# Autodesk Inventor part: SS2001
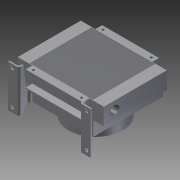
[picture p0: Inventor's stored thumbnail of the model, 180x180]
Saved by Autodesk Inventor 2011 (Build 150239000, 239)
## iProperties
Created: 2011-08
Part Number: SS2001
Document SubType Name: Modeling
Designer: khramov
Density: 1 g/cm^3
Author: khramov
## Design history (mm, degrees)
sketch "Эскиз1"
  geometry: L1 (0, 0)-(318, 0); L2 (318, 0)-(318, -283); L3 (318, -283)-(0, -283); L4 (0, -283)-(0, 0)
  constraints: 8 end point, 2 parallel, 1 horizontal, 1 perpendicular
  dimensions: "d0" = 318 distance of L1.start L1.end; "d1" = 283 distance of L3.end L1.start
extrude "Выдавливание1" new body sketch "Эскиз1" distance "d2" = 63; taper "d3" = 0 deg
sketch "Эскиз2"
  geometry: L1 (-63, 283)-(-63, 0) reference; L2 (0, 283)-(0, 0) reference; L3 (0, 283)-(-63, 283) reference; L4 (-58, 283)-(-5, 283); L5 (-5, 283)-(-5, 258); L6 (-5, 258)-(-58, 258); L7 (-58, 258)-(-58, 283); L8 (-63, 0)-(-63, 283) reference; L9 (-63, 141.5)-(63.697, 141.5); L10 (0, 0)-(-63, 0); L11 (-58, 0)-(-5, 0); L12 (-5, 0)-(-5, 25); L13 (-5, 25)-(-58, 25); L14 (-58, 25)-(-58, 0)
  constraints: 20 end point, 4 symmetric about line, 2 parallel, 2 perpendicular, 2 point on line, 1 horizontal, 1 midpoint
  dimensions: "d4" = 5 distance between parallel lines of L7 L1; "d5" = 5 distance between parallel lines of L2 L5; "d6" = 25 distance between parallel lines of L3 L6
extrude "Выдавливание2" cut sketch "Эскиз2" stored distance "d7" = 63; taper "d8" = 0 deg
sketch "Эскиз3"
  geometry: L1 (0, 0)-(54, 0); L2 (54, 0)-(54, -25); L3 (54, -25)-(0, -25); L4 (0, -25)-(0, 0); L5 (318, 0)-(264, 0); L6 (264, 0)-(264, -25); L7 (264, -25)-(318, -25); L8 (318, -25)-(318, 0); L9 (0, -141.5)-(444.092, -141.5); L10 (0, -283)-(54, -283); L11 (54, -283)-(54, -258); L12 (54, -258)-(0, -258); L13 (0, -258)-(0, -283); L14 (318, -283)-(264, -283); L15 (264, -283)-(264, -258); L16 (264, -258)-(318, -258); L17 (318, -258)-(318, -283)
  constraints: 34 end point, 8 symmetric about line, 4 parallel, 3 perpendicular, 2 horizontal
  dimensions: "d9" = 25 distance of L1.end L2.end; "d10" = 25 distance of L5.end L6.end; "d11" = 210 distance between parallel lines of L6 L2; "d13" = 54 distance of L2.end L3.end
extrude "Выдавливание3" cut sketch "Эскиз3" stored distance "d14" = 0; taper "d15" = 0 deg
sketch "Эскиз4"
  geometry: L1 (54, 0)-(54, -25) reference; L2 (54, 0)-(264, 0) reference; L3 (70, -12.5)-(248, -12.5); L4 (248, -12.5)-(248, -270.5); L5 (248, -270.5)-(70, -270.5); L6 (70, -270.5)-(70, -12.5); C1 r 4.5 at (70, -12.5); C2 r 4.5 at (248, -12.5); C3 r 4.5 at (248, -270.5); C4 r 4.5 at (70, -270.5); 1 further point
  constraints: 8 end point, 4 centre point, 4 coincident, 2 parallel, 1 horizontal, 1 perpendicular
  dimensions: "d16" = 9 diameter of C1; "d17" = 9 diameter of C2; "d18" = 9 diameter of C3; "d19" = 9 diameter of C4; "d20" = 258 distance of L5.end L3.start; "d21" = 178 distance of L3.start L3.end; "d22" = 16 distance between parallel lines of L6 L1; "d23" = 12.5 distance between parallel lines of L3 L2
extrude "Выдавливание4" cut sketch "Эскиз4" distance "d24" = 10; taper "d25" = 0 deg
sketch "Эскиз5"
  geometry: L1 (54, 0)-(54, -25) reference; L2 (54, -25)-(0, -25) reference; L3 (0, -258)-(54, -258) reference; L4 (264, -25)-(264, 0) reference; L5 (42, -27)-(276, -27); L6 (276, -27)-(276, -256); L7 (276, -256)-(42, -256); L8 (42, -256)-(42, -27); 1 further point
  constraints: 8 end point, 2 parallel, 1 horizontal, 1 perpendicular
  dimensions: "d26" = 2 distance between parallel lines of L5 L2; "d27" = 2 distance between parallel lines of L3 L7; "d28" = 12 distance between parallel lines of L1 L8; "d29" = 12 distance between parallel lines of L6 L4
extrude "Выдавливание5" cut sketch "Эскиз5" distance "d30" = 2; taper "d31" = 0 deg
sketch "Эскиз6"
  geometry: L1 (-264, 0)-(-264, -25) reference; L2 (-279, 0)-(-39, 0); L3 (-39, 0)-(-39, -258); L4 (-39, -258)-(-279, -258); L5 (-279, -258)-(-279, 0); 1 further point
  constraints: 8 end point, 2 parallel, 1 horizontal, 1 perpendicular
  dimensions: "d32" = 210 distance of point (-54, 0) L1.start (derived); "d33" = 240 distance between parallel lines of L3 L5; "d34" = 15 distance between parallel lines of L1 L5; "d35" = 258 distance of L4.end L2.start
extrude "Выдавливание6" join sketch "Эскиз6" distance "d36" = 53; taper "d37" = 0 deg
sketch "Эскиз7"
  geometry: L1 (-279, 0)-(-39, -258); L2 (-39, 0)-(-279, -258); C1 r 100 at (-159, -129); 1 further point
  constraints: 4 end point, 1 centre point, 1 midpoint
  dimensions: "d38" = 200 diameter of C1
extrude "Выдавливание7" join sketch "Эскиз7" distance "d39" = 54; taper "d40" = 0 deg
sketch "Эскиз8"
  geometry: L1 (-276.5, -265)-(-276.5, -288); L2 (-283.5, -295)-(-311.5, -295); L3 (-311.5, -295)-(-311.5, -300); L4 (-311.5, -300)-(-278.5, -300); L5 (-271.5, -293)-(-271.5, -270); L6 (-264.5, -263)-(-264, -263); L7 (-264, -258)-(-264, -263); L8 (-269.5, -258)-(-264, -258); L9 (-159, -129)-(-159, -359.645); L10 (-296.5, -281.5)-(-296.5, -330.929); L11 (-41.5, -265)-(-41.5, -288); L12 (-46.5, -293)-(-46.5, -270); L13 (-6.5, -300)-(-39.5, -300); L14 (-34.5, -295)-(-6.5, -295); L15 (-21.5, -281.5)-(-21.5, -330.929); L16 (-6.5, -295)-(-6.5, -300); L17 (-53.5, -263)-(-54, -263); L18 (-54, -258)-(-54, -263); L19 (-48.5, -258)-(-54, -258); A1 r 7 centre (-283.5, -288) between (-283.5, -295) and (-276.5, -288); A2 r 7 centre (-278.5, -293) between (-278.5, -300) and (-271.5, -293); A3 r 7 centre (-264.5, -270) between (-264.5, -263) and (-271.5, -270); A4 r 7 centre (-269.5, -265) between (-269.5, -258) and (-276.5, -265); A5 r 7 centre (-39.5, -293) between (-46.5, -293) and (-39.5, -300); A6 r 7 centre (-34.5, -288) between (-41.5, -288) and (-34.5, -295); A7 r 7 centre (-53.5, -270) between (-46.5, -270) and (-53.5, -263); A8 r 7 centre (-48.5, -265) between (-41.5, -265) and (-48.5, -258); 2 further points
  constraints: 38 end point, 19 symmetric about line, 16 point on circle, 8 centre point, 8 tangent, 4 parallel, 4 point on line, 3 equal radius, 1 perpendicular, 4 other
  dimensions: "d41" = 5 distance of L2.end L3.end; "d42" = 5 distance between parallel lines of L1 L5; "d43" = 5 distance between parallel lines of L6 L8; "d45" = 35 distance of point (-276.5, -295) L2.end; "d46" = 15 distance between parallel lines of L10 L3; "d47" = 20 distance between parallel lines of L1 L10 (derived); "d48" = 7 radius of A1; "d49" = 275 distance between parallel lines of L15 L10
extrude "Выдавливание8" join sketch "Эскиз8" distance "d50" = 30; taper "d52" = 0 deg; dims "d51" = 126, "d53" = 0
sketch "Эскиз9"
  geometry: L1 (-30, 42)-(-27.687, 27.383); L2 (-27.687, 27.383)-(0, 12.765); L3 (0, 30)-(0, 7) reference; L4 (0, 42)-(0, 12.765); L5 (-30, 42)-(0, 42); L6 (0, 42)-(-30, 42) reference; L7 (-30, 42)-(-83, 42) reference; L8 (-67.613, 42)-(-67.613, 27.383); L9 (0, 30)-(-156, 30) reference; L10 (-67.613, 27.383)-(-156, 17); L11 (-156, 7)-(-156, 30) reference; L12 (-156, 42)-(-67.613, 42); L13 (0, 37)-(-156, 37) reference; L14 (-156, 42)-(-156, 17); 1 further point
  constraints: 16 end point, 3 collinear, 3 point on line, 1 parallel, 1 perpendicular
extrude "Выдавливание9" cut sketch "Эскиз9" stored distance "d54" = 60; taper "d55" = 0 deg
sketch "Эскиз10"
  geometry: L1 (-10, 5)-(-10, 0) reference; L2 (78.387, 5)-(78.387, -9.617); L3 (78.387, -2)-(78.387, 5) reference; L4 (78.387, -9.617)-(-10, -20); L5 (78.387, -9.617)-(-10, -20) reference; L6 (-10, -20)-(-10, 5); L7 (78.387, 5)-(-10, 5); L8 (116, 5)-(118.313, -9.617); L9 (118.313, -9.617)-(117.108, -2) reference; L10 (118.313, -9.617)-(146, -25); L11 (146, -25)-(146, 5); L12 (146, -25)-(-10, -25) reference; L13 (146, 5)-(116, 5); 1 further point
  constraints: 16 end point, 3 collinear, 2 perpendicular, 1 parallel
extrude "Выдавливание10" cut sketch "Эскиз10" distance "d56" = 60; taper "d57" = 0 deg
sketch "Эскиз11"
  geometry: L1 (33, 0)-(33, 156) reference; L2 (18, 143)-(-257, 143); L3 (-257, 143)-(-257, 17); L4 (-257, 17)-(18, 17); L5 (18, 17)-(18, 143); L6 (-14.5, 146)-(-224.5, 146) reference; C1 r 6.5 at (18, 143); C2 r 6.5 at (18, 17); C3 r 6.5 at (-257, 17); C4 r 6.5 at (-257, 143); 1 further point
  constraints: 8 end point, 4 centre point, 4 coincident, 2 parallel, 1 horizontal, 1 perpendicular
  dimensions: "d58" = 13 diameter of C2; "d59" = 13 diameter of C1; "d60" = 13 diameter of C3; "d61" = 13 diameter of C4; "d62" = 275 distance of L2.start L2.end; "d63" = 126 distance of L4.end L2.start; "d64" = 3 distance from line of L6 C1.centre; "d65" = 15 distance from line of C1.centre L1
extrude "Выдавливание11" cut sketch "Эскиз11" distance "d66" = 10; taper "d67" = 0 deg
sketch "Эскиз12"
  geometry: L1 (-63, 0)-(0, 0) reference; L2 (-63, 233)-(-63, 0) reference; L3 (-31.5, 0)-(-31.5, 41.5); L4 (83, -42)-(-73, -42) reference; 2 further points
  constraints: 2 end point, 1 coincident, 1 midpoint, 1 parallel
  dimensions: "d69" = 83.5 distance from line of point (-31.5, 41.5) L4
hole "Отверстие1" sketch "Эскиз12" at (-31.5, 41.5) diameter "d70" = 30.291; stored, may be unused: countersink angle "d74" = 90 deg, drill point angle "d76" = 118 deg; dims "d71" = 40, "d72" = 34, "d73" = 2, "d75" = 50
sketch "Эскиз13"
  geometry: L1 (0, 233)-(63, 233) reference; L2 (31.5, 233)-(31.5, 198.5); C1 r 15.146 at (31.5, 41.5) reference; 2 further points
  constraints: 2 end point, 1 coincident, 1 midpoint, 1 perpendicular
  dimensions: "d77" = 157 distance of C1.centre point (31.5, 198.5)
hole "Отверстие2" sketch "Эскиз13" at (31.5, 198.5) diameter "d78" = 30.291; stored, may be unused: countersink angle "d82" = 90 deg, drill point angle "d84" = 118 deg; dims "d79" = 40, "d80" = 34, "d81" = 2, "d83" = 50
node "Твердое тело1"
